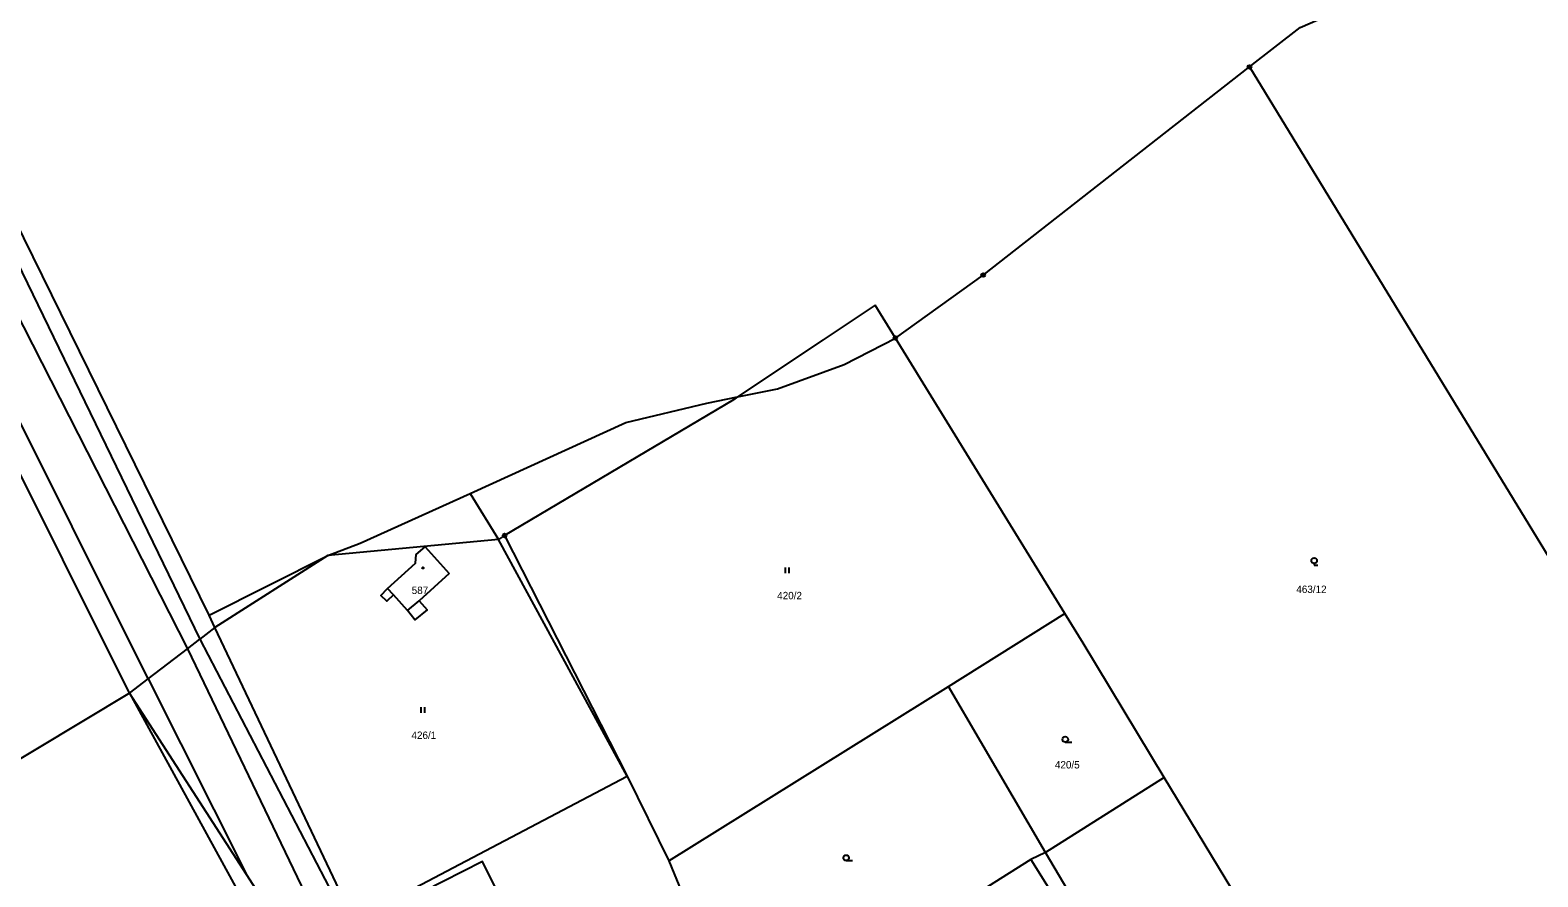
# Model space of a CAD drawing. Extents: x -745926 to -742978, y -968282 to -965689.
# Drawn here: x -745176.7 to -744972.9, y -966712.9 to -966598.4 of the extents above; entities that cross this region are included whole.
import ezdxf

# ---------------------------------------------------------------- set-up
doc = ezdxf.new("R2010")
doc.units = 0
for name, color, linetype in [('Hranice parcel', 7, 'Continuous'), ('Parcelní čísla', 7, 'Continuous'), ('Vnitřní kresba', 7, 'Continuous'), ('Značky bodu BP', 7, 'Continuous'), ('Značky budov', 7, 'Continuous'), ('Značky kultur', 7, 'Continuous')]:
    doc.layers.add(name, color=color, linetype=linetype)

msp = doc.modelspace()

# ---------------------------------------------------------------- linework, layer by layer
at = {"layer": 'Hranice parcel'}
for p, q in [((-745163.29, -966688.08), (-745214.98, -966584.42)), ((-745047.89, -966631.54), (-745011.89, -966603.4)), ((-745011.89, -966603.4), (-744946.43, -966710.72)), ((-745059.76, -966640.06), (-745047.89, -966631.54)), ((-745059.76, -966640.06), (-745062.5, -966635.61)), ((-745036.83, -966677.31), (-745059.76, -966640.06)), ((-745112.58, -966666.75), (-745096.03, -966699.27)), ((-745052.58, -966687.14), (-745036.83, -966677.31)), ((-745153.75, -966680.76), (-745134.06, -966718.61)), ((-745090.38, -966710.74), (-745052.58, -966687.14)), ((-745039.46, -966709.62), (-745052.58, -966687.14)), ((-745096.03, -966699.27), (-745090.38, -966710.74)), ((-745023.44, -966699.46), (-745039.46, -966709.62)), ((-745002.62, -966733.75), (-745023.44, -966699.46))]:
    msp.add_line(p, q, dxfattribs=at)
for points in [[(-745275.18, -966443.55), (-745204.63, -966575.83), (-745153.75, -966680.76)], [(-745011.89, -966603.4), (-745005.05, -966598.06), (-744977.86, -966586.22)], [(-745062.5, -966635.61), (-745069.53, -966640.3), (-745081.08, -966648.02), (-745081.63, -966648.39), (-745112.58, -966666.75)], [(-745112.58, -966666.75), (-745113.4, -966667.27), (-745136.48, -966669.46), (-745151.72, -966679.2), (-745153.75, -966680.76)], [(-745120.05, -966671.87), (-745124.14, -966675.56), (-745123.03, -966676.8), (-745124.71, -966678.16), (-745125.68, -966676.88), (-745127.58, -966674.75), (-745128.5, -966675.63), (-745129.3, -966674.86), (-745128.39, -966673.92), (-745124.64, -966670.47), (-745124.54, -966669.31), (-745123.33, -966668.3), (-745120.05, -966671.87)], [(-745023.44, -966699.46), (-745034.38, -966681.29), (-745036.83, -966677.31)], [(-745163.29, -966688.08), (-745160.73, -966686.11), (-745155.45, -966682.06), (-745153.75, -966680.76)], [(-745163.29, -966688.08), (-745207.73, -966714.8), (-745250.26, -966736.5)], [(-745140.83, -966722.83), (-745147.45, -966712.59), (-745163.29, -966688.08)], [(-745134.06, -966718.61), (-745133.29, -966718.19), (-745129.07, -966716.66), (-745096.03, -966699.27)], [(-745099.55, -966753.7), (-745113.13, -966726.94), (-745108.67, -966724.69), (-745115.57, -966710.82), (-745126.19, -966716.22)], [(-745090.38, -966710.74), (-745085.52, -966722.6), (-745081.39, -966735.5)], [(-745039.46, -966709.62), (-745041.45, -966710.54), (-745047.3, -966714.23), (-745062.3, -966723.69), (-745081.39, -966735.5)], [(-745018.23, -966743.31), (-745019.27, -966743.78), (-745039.46, -966709.62)]]:
    msp.add_lwpolyline(points, dxfattribs=at)
at = {"layer": 'Vnitřní kresba'}
for p, q in [((-745213.03, -966569.01), (-745155.45, -966682.06)), ((-745160.73, -966686.11), (-745212.48, -966582.61)), ((-745152.51, -966677.53), (-745197.01, -966586.93)), ((-745066.69, -966643.62), (-745059.76, -966640.06)), ((-745075.69, -966646.94), (-745066.69, -966643.62)), ((-745081.08, -966648.02), (-745075.69, -966646.94)), ((-745096.2, -966651.48), (-745085.24, -966648.86)), ((-745085.24, -966648.86), (-745081.08, -966648.02)), ((-745117.25, -966661.06), (-745096.2, -966651.48)), ((-745132.1, -966667.79), (-745117.25, -966661.06)), ((-745117.25, -966661.06), (-745113.4, -966667.27)), ((-745136.48, -966669.46), (-745132.1, -966667.79)), ((-745096.03, -966699.27), (-745113.4, -966667.27)), ((-745152.51, -966677.53), (-745136.48, -966669.46)), ((-745127.58, -966674.75), (-745128.39, -966673.92)), ((-745125.68, -966676.88), (-745124.14, -966675.56)), ((-745151.72, -966679.2), (-745152.51, -966677.53)), ((-745134.5, -966715.55), (-745151.72, -966679.2)), ((-745155.45, -966682.06), (-745137.43, -966719.51)), ((-745160.73, -966686.11), (-745147.45, -966712.59)), ((-745163.29, -966688.08), (-745143.49, -966724.15)), ((-745041.45, -966710.54), (-745033.95, -966722.44))]:
    msp.add_line(p, q, dxfattribs=at)
at = {"layer": 'Značky bodu BP'}
for centre, radius in [((-745011.89, -966603.4), 0.25), ((-745011.89, -966603.4), 0.0152), ((-745047.89, -966631.54), 0.25), ((-745047.89, -966631.54), 0.0152), ((-745059.76, -966640.06), 0.25), ((-745059.76, -966640.06), 0.0152), ((-745112.58, -966666.75), 0.25), ((-745112.58, -966666.75), 0.0152)]:
    msp.add_circle(centre, radius, dxfattribs=at)
at = {"layer": 'Značky budov'}
msp.add_circle((-745123.62, -966671.13), 0.0875, dxfattribs=at)
at = {"layer": 'Značky kultur'}
for p, q in [((-745074.6, -966671.82), (-745074.6, -966671.07)), ((-745074.09, -966671.82), (-745074.09, -966671.07)), ((-745003.15, -966670.53), (-745003.15, -966670.78)), ((-745003.15, -966670.78), (-745002.65, -966670.78)), ((-745123.85, -966690.7), (-745123.85, -966689.95)), ((-745123.34, -966690.7), (-745123.34, -966689.95)), ((-745036.79, -966694.69), (-745035.91, -966694.69)), ((-745066.41, -966710.7), (-745065.53, -966710.7))]:
    msp.add_line(p, q, dxfattribs=at)
for centre in [(-745003.15, -966670.16), (-745036.79, -966694.31), (-745066.41, -966710.32)]:
    msp.add_circle(centre, 0.375, dxfattribs=at)

# ---------------------------------------------------------------- texts
at = {"layer": 'Parcelní čísla'}
for s, p in [('587', (-745125.13, -966674.66)), ('463/12', (-745005.56, -966674.52)), ('420/2', (-745075.73, -966675.37)), ('426/1', (-745125.16, -966694.25)), ('420/5', (-745038.19, -966698.24))]:
    msp.add_text(s, height=1, dxfattribs=at).set_placement(p)

doc.saveas('drawing.dxf')
